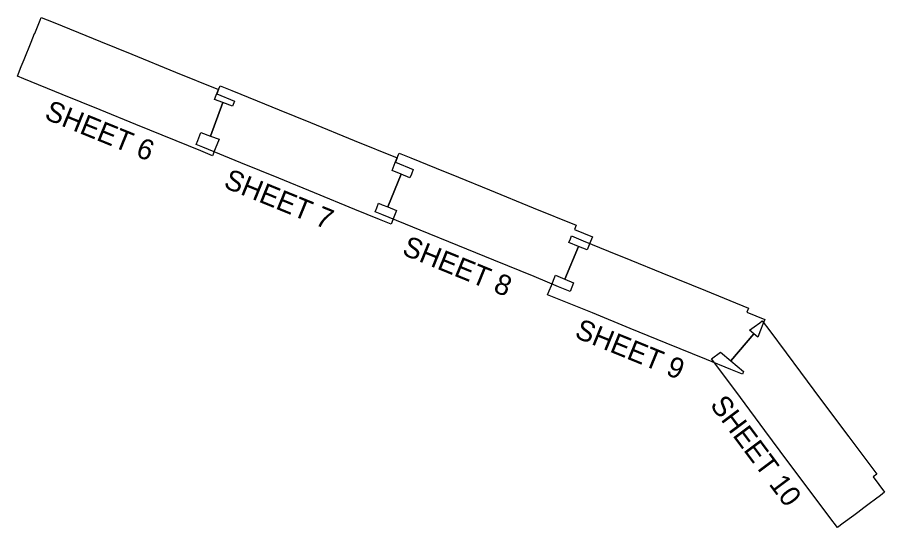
# Model space of a CAD drawing. Extents: x 2165417 to 2172214, y 205819 to 209814.
import ezdxf

# ---------------------------------------------------------------- set-up
doc = ezdxf.new("R2010")
doc.units = 0
doc.layers.add('RD_PD_Final_LnLine', color=7, linetype='Continuous')
doc.layers.add('RD_SHT_MatchLine', color=7, linetype='Continuous')

msp = doc.modelspace()

# ---------------------------------------------------------------- linework, layer by layer
at = {"layer": 'RD_SHT_MatchLine'}
for points in [[(2165417.4, 209354), (2165448.2, 209429.6), (2165470.8, 209485.2), (2165525.8, 209620.1), (2165525.8, 209620.1), (2165553.1, 209687.1), (2165553.1, 209687.1), (2165553.9, 209689), (2165575.2, 209741.3), (2165595.5, 209791.3), (2165605, 209814.4), (2165697.6, 209776.7), (2165896.3, 209695.8), (2166069.4, 209625.3), (2166313.3, 209525.9), (2166656.3, 209386.2), (2166993.4, 209248.9), (2166980.2, 209216.5), (2167119.9, 209159.6), (2167103.4, 209119.3), (2167027.1, 209146.9), (2167027.1, 209146.9), (2166932.3, 208885.6), (2166932.3, 208885.6), (2166998.5, 208861.6), (2166967.4, 208785.3), (2166945.5, 208731.6), (2166854.9, 208768.5), (2166662.5, 208846.8), (2166346.2, 208975.7), (2166066.1, 209089.8), (2165769.1, 209210.7), (2165469.2, 209332.9)], [(2166818.1, 208818.5), (2166831, 208850.1), (2166856.6, 208913), (2166932.3, 208885.6), (2166932.3, 208885.6), (2167027.1, 209146.9), (2167027.1, 209146.9), (2166961.6, 209170.7), (2166975.9, 209205.9), (2166996.2, 209255.9), (2167005.7, 209279), (2167098.3, 209241.3), (2167297, 209160.3), (2167470.1, 209089.8), (2167714, 208990.5), (2168057, 208850.8), (2168394.1, 208713.5), (2168380.9, 208681.1), (2168520.6, 208624.2), (2168505.5, 208587.2), (2168494.1, 208559.3), (2168424.6, 208587.6), (2168424.6, 208587.6), (2168319.8, 208330.2), (2168389.3, 208301.8), (2168368.1, 208249.9), (2168346.2, 208196.1), (2168255.6, 208233), (2168063.2, 208311.4), (2167746.9, 208440.2), (2167466.8, 208554.3), (2167169.8, 208675.3), (2166869.9, 208797.5)], [(2168221.4, 208291.5), (2168234.3, 208323.1), (2168248.9, 208359), (2168277, 208347.6), (2168319.8, 208330.2), (2168424.6, 208587.6), (2168424.6, 208587.6), (2168353.8, 208616.5), (2168379.2, 208678.9), (2168399.6, 208728.8), (2168409, 208752), (2168501.6, 208714.3), (2168700.4, 208633.3), (2168873.4, 208562.8), (2169117.3, 208463.5), (2169460.3, 208323.8), (2169797.4, 208186.5), (2169784.2, 208154.1), (2169923.9, 208097.2), (2169908.9, 208060.2), (2169881.9, 207994.1), (2169813.8, 208021.8), (2169813.8, 208021.8), (2169708.9, 207764.3), (2169708.9, 207764.3), (2169777, 207736.6), (2169749.6, 207669.1), (2169659, 207706), (2169466.6, 207784.4), (2169150.2, 207913.2), (2168870.1, 208027.3), (2168573.1, 208148.3), (2168273.2, 208270.4)], [(2169572.4, 207643.1), (2169585.3, 207674.7), (2169602.2, 207716.1), (2169624.1, 207770), (2169634.2, 207794.8), (2169708.9, 207764.3), (2169708.9, 207764.3), (2169813.8, 208021.8), (2169739.1, 208052.3), (2169751, 208081.4), (2169760, 208103.6), (2169852.6, 208065.8), (2170051.3, 207984.9), (2170224.4, 207914.4), (2170468.3, 207815.1), (2170811.3, 207675.4), (2171148.4, 207538.1), (2171135.2, 207505.6), (2171274.9, 207448.7), (2171259.8, 207411.8), (2171240.7, 207364.9), (2171219.1, 207311.8), (2171188.9, 207337.3), (2171188.9, 207337.3), (2171009.3, 207125), (2171108.8, 207041), (2171100.5, 207020.7), (2171009.9, 207057.6), (2170817.5, 207136), (2170501.2, 207264.8), (2170221.1, 207378.9), (2169924.1, 207499.9), (2169624.2, 207622)], [(2170856.8, 207141.7), (2170927.4, 207194.4), (2171009.3, 207125), (2171009.3, 207125), (2171188.9, 207337.3), (2171188.9, 207337.3), (2171170.4, 207352.9), (2171156.1, 207365.1), (2171192, 207391.9), (2171235.2, 207424.1), (2171255.2, 207439.1), (2171315, 207359), (2171443.4, 207187), (2171555.2, 207037.2), (2171712.7, 206826.2), (2171934.3, 206529.4), (2172152, 206237.8), (2172124, 206216.8), (2172214.2, 206095.9), (2172182.2, 206072.1), (2172141.6, 206041.7), (2172092.2, 206004.9), (2172051.6, 205974.6), (2172003.4, 205938.6), (2171971.6, 205914.8), (2171890.3, 205854.2), (2171843.8, 205819.5), (2171785.3, 205897.8), (2171661, 206064.3), (2171456.7, 206338), (2171275.8, 206580.4), (2171083.9, 206837.4), (2170890.2, 207096.9)]]:
    msp.add_lwpolyline(points, close=True, dxfattribs=at)

# ---------------------------------------------------------------- texts
at = {"layer": 'RD_PD_Final_LnLine'}
for s, rotation, p in [('SHEET 6', 337.83882, (2165621.6, 209022.5)), ('SHEET 7', 337.83882, (2167025.8, 208485.6)), ('SHEET 8', 337.83882, (2168423.9, 207960.7)), ('SHEET 9', 337.83882, (2169776.6, 207311.6)), ('SHEET 10', 306.74115, (2170840, 206779.6))]:
    msp.add_text(s, height=160, rotation=rotation, dxfattribs=at).set_placement(p)

doc.saveas('drawing.dxf')
